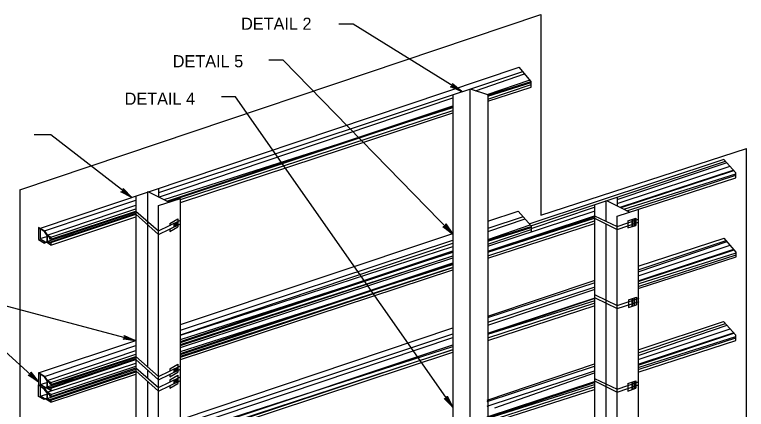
# Model space of a CAD drawing. Extents: x 650495 to 652241, y 298458 to 299646.
# Drawn here: x 651654.1 to 651834.8, y 298779.7 to 298877.1 of the extents above; entities that cross this region are included whole.
import ezdxf

# ---------------------------------------------------------------- set-up
doc = ezdxf.new("R2010")
doc.units = 0
doc.layers.add('2', color=7, linetype='Continuous')
doc.layers.add('3', color=7, linetype='Continuous')

# ---------------------------------------------------------------- blocks, each defined once
blk = doc.blocks.new('RARROW')
at = {"layer": '3'}
blk.add_lwpolyline([(-2.2695, 0.285), (-2.184875, 0.12075), (0, 0), (-2.2695, 0.285), (-2.38575, 0.384625), (0, 0), (-2.183125, -0.108), (-2.262875, -0.2705), (0, 0), (-2.38575, -0.379125), (-2.262875, -0.2705)], dxfattribs=at)

msp = doc.modelspace()

# ---------------------------------------------------------------- linework, layer by layer
at = {"layer": '2'}
for p, q in [((651655.44, 298833.88), (651784.06, 298877.13)), ((651784.06, 298877.13), (651784.06, 298827.63)), ((651737.69, 298874.75), (651734.19, 298874.75)), ((651764.56, 298858.13), (651737.69, 298874.75)), ((651720.44, 298865.88), (651716.94, 298865.88)), ((651762.31, 298823), (651720.44, 298865.88)), ((651660.31, 298824.38), (651778.69, 298864.13)), ((651779.56, 298863), (651689.69, 298833.13)), ((651767.97, 298858.31), (651780.06, 298862.5)), ((651781.69, 298860.63), (651778.69, 298864.13)), ((651770.81, 298857.42), (651781.44, 298861)), ((651781.69, 298859.25), (651781.69, 298860.75)), ((651770.94, 298857.25), (651781.69, 298860.63)), ((651770.94, 298857), (651781.69, 298860.38)), ((651770.94, 298856.25), (651781.69, 298859.88)), ((651770.94, 298855.75), (651781.69, 298859.25)), ((651762.31, 298857.27), (651762.31, 298770.13)), ((651766.56, 298858.68), (651766.56, 298771.88)), ((651770.94, 298857.38), (651766.67, 298858.72)), ((651770.94, 298857.38), (651770.94, 298770.38)), ((651689.69, 298832.13), (651762.31, 298856.63)), ((651708.69, 298856.88), (651705.19, 298856.88)), ((651762.31, 298780.25), (651708.69, 298856.88)), ((651691.06, 298831.5), (651762.31, 298854.25)), ((651691.69, 298831.13), (651762.31, 298854.63)), ((651692.06, 298831), (651762.31, 298854.38)), ((651695.06, 298831.5), (651762.31, 298853.5)), ((651695.06, 298830.75), (651762.31, 298852.88)), ((651663.06, 298847.5), (651658.94, 298847.5)), ((651683.06, 298832), (651663.06, 298847.5)), ((651784.06, 298827.63), (651834.81, 298844.13)), ((651834.81, 298733.38), (651834.81, 298844.13)), ((651781.19, 298825.5), (651829.31, 298841.5)), ((651781.56, 298825), (651829.69, 298841)), ((651832.19, 298838.13), (651829.19, 298841.5)), ((651802.94, 298831.5), (651830.06, 298840.63)), ((651802.94, 298830.5), (651830.81, 298839.75)), ((651803.69, 298829.63), (651831.56, 298838.75)), ((651803.94, 298829.5), (651831.69, 298838.63)), ((651804.56, 298829.13), (651832.19, 298837.88)), ((651805.31, 298828.75), (651832.19, 298837.5)), ((651832.19, 298836.88), (651832.19, 298838.13)), ((651802.94, 298827.38), (651832.19, 298836.88)), ((651655.44, 298834), (651655.44, 298674)), ((651689.69, 298834.25), (651689.69, 298832.13)), ((651684.06, 298832.38), (651684.06, 298664.13)), ((651687.06, 298833.5), (651692.31, 298830.88)), ((651687.06, 298790.13), (651687.06, 298833.5)), ((651689.69, 298830), (651695.06, 298831.75)), ((651695.06, 298661.88), (651695.06, 298831.75)), ((651802.94, 298832), (651802.94, 298830)), ((651661.56, 298823.75), (651684.06, 298831.38)), ((651662.19, 298822.75), (651684.06, 298830.13)), ((651689.69, 298659.25), (651689.69, 298830)), ((651797.31, 298830.25), (651797.31, 298704.5)), ((651800.19, 298826.13), (651800.19, 298831.25)), ((651800.31, 298831.25), (651806.06, 298828.38)), ((651662.19, 298821.13), (651684.06, 298828.5)), ((651663.06, 298822.25), (651684.06, 298829.25)), ((651663.06, 298821.75), (651684.06, 298828.63)), ((651684.06, 298828.63), (651689.69, 298823.75)), ((651770.94, 298820), (651797.44, 298828.75)), ((651770.94, 298826.13), (651778.44, 298828.63)), ((651778.44, 298828.63), (651781.69, 298825)), ((651781.69, 298824.38), (651797.31, 298829.63)), ((651808.19, 298702.25), (651808.19, 298829.13)), ((651662.81, 298821), (651684.06, 298828.13)), ((651663.06, 298820.88), (651684.06, 298827.88)), ((651663.06, 298820.25), (651684.06, 298827.25)), ((651684.06, 298827.88), (651689.69, 298822.88)), ((651684.06, 298827.25), (651684.06, 298827.25)), ((651689.69, 298823.75), (651695.06, 298826.38)), ((651692.44, 298825.63), (651694.44, 298826.75)), ((651694.44, 298826.75), (651694.44, 298824.75)), ((651770.94, 298818.75), (651797.31, 298827.5)), ((651779.69, 298827.25), (651770.94, 298824.38)), ((651770.94, 298818.5), (651797.31, 298827.25)), ((651770.94, 298818.5), (651797.31, 298826.88)), ((651770.94, 298823.63), (651780.19, 298826.75)), ((651797.31, 298827.5), (651802.94, 298824.88)), ((651797.31, 298826.88), (651802.94, 298824.13)), ((651802.94, 298699.63), (651802.94, 298827.38)), ((651802.94, 298824.88), (651808.19, 298826.63)), ((651805.56, 298826.25), (651807.56, 298826.88)), ((651806.56, 298826.63), (651806.56, 298824.75)), ((651806.81, 298826.63), (651806.81, 298824.88)), ((651807.19, 298826.75), (651807.19, 298825)), ((651807.56, 298826.88), (651807.56, 298825.13)), ((651660.06, 298824.63), (651660.06, 298824.63)), ((651661.56, 298823.75), (651660.06, 298824.63)), ((651660.06, 298824.63), (651660.06, 298821.63)), ((651660.06, 298824.63), (651661.56, 298823.75)), ((651689.69, 298822.88), (651695.06, 298825.5)), ((651692.44, 298825.63), (651692.44, 298825)), ((651692.44, 298823.63), (651694.44, 298824.75)), ((651693.44, 298825.63), (651693.44, 298824.75)), ((651693.69, 298825.75), (651693.69, 298824.88)), ((651694.06, 298825.88), (651694.06, 298825.13)), ((651694.31, 298826), (651694.31, 298825.25)), ((651770.94, 298817.63), (651797.31, 298826.25)), ((651770.94, 298817), (651797.31, 298825.63)), ((651770.94, 298821.63), (651781.44, 298825.25)), ((651770.94, 298821.5), (651781.69, 298824.88)), ((651770.94, 298821.25), (651781.69, 298824.63)), ((651781.69, 298825), (651781.69, 298823.5)), ((651800.19, 298702), (651800.19, 298825.5)), ((651802.94, 298824.13), (651808.19, 298825.88)), ((651805.56, 298826.25), (651805.56, 298824.5)), ((651805.56, 298824.5), (651807.56, 298825.13)), ((651660.44, 298824.25), (651660.44, 298821.75)), ((651661.44, 298823.63), (651660.44, 298824.25)), ((651661.44, 298823.63), (651662.06, 298822.63)), ((651661.56, 298823.75), (651662.19, 298822.75)), ((651662.06, 298822.75), (651662.06, 298821.13)), ((651662.19, 298821.13), (651668.69, 298823.25)), ((651663.06, 298822.25), (651662.19, 298822.75)), ((651663.06, 298822.25), (651669.56, 298824.38)), ((651663.06, 298821.75), (651669.56, 298823.88)), ((651692.44, 298824.25), (651692.44, 298823.63)), ((651695.06, 298800.63), (651762.31, 298823.13)), ((651770.94, 298820.5), (651781.69, 298824.13)), ((651660.06, 298821.63), (651661.56, 298820.75)), ((651660.44, 298821.88), (651662.06, 298822.38)), ((651661.69, 298821), (651660.44, 298821.75)), ((651661.44, 298821.25), (651660.44, 298821.75)), ((651661.69, 298821), (651662.06, 298821.13)), ((651662.81, 298822.13), (651662.19, 298822.5)), ((651662.81, 298822.13), (651662.19, 298822.5)), ((651662.19, 298822.5), (651662.19, 298821.13)), ((651662.81, 298820.75), (651662.19, 298821.13)), ((651662.81, 298822.13), (651662.81, 298821.88)), ((651662.81, 298821.75), (651662.81, 298822.13)), ((651663.06, 298821.75), (651662.81, 298821.88)), ((651663.06, 298821.75), (651662.81, 298821.75)), ((651662.81, 298821), (651662.81, 298820.75)), ((651663.06, 298820.88), (651662.81, 298821)), ((651662.81, 298821), (651662.81, 298820.75)), ((651663.06, 298820.88), (651662.81, 298821)), ((651663.06, 298822.25), (651663.06, 298821.75)), ((651663.06, 298822.25), (651663.06, 298821.75)), ((651695.06, 298799.25), (651762.31, 298821.5)), ((651808.31, 298815.13), (651829.31, 298822)), ((651808.31, 298814.25), (651829.81, 298821.38)), ((651808.31, 298813.75), (651830.06, 298821.13)), ((651832.31, 298818.5), (651829.31, 298822)), ((651662.06, 298820.88), (651661.56, 298820.75)), ((651663.06, 298820.25), (651662.06, 298820.88)), ((651663.06, 298820.88), (651663.06, 298820.25)), ((651663.06, 298820.88), (651663.06, 298820.25)), ((651695.06, 298798.13), (651762.31, 298820.75)), ((651695.06, 298798), (651762.31, 298819.88)), ((651808.31, 298812.75), (651830.81, 298820.25)), ((651808.31, 298811.5), (651831.69, 298819.25)), ((651808.31, 298811.38), (651831.81, 298819.13)), ((651695.06, 298796.5), (651762.31, 298818.88)), ((651695.06, 298796.25), (651762.31, 298818.63)), ((651695.06, 298797), (651762.31, 298818.5)), ((651695.06, 298795.5), (651762.31, 298817.63)), ((651695.06, 298795.75), (651762.31, 298817.63)), ((651808.31, 298810.75), (651832.31, 298818.38)), ((651808.31, 298810.13), (651832.31, 298817.88)), ((651808.31, 298809.63), (651832.31, 298817.38)), ((651832.31, 298817.38), (651832.31, 298818.5)), ((651695.06, 298795), (651762.31, 298817.13)), ((651695.06, 298793.5), (651762.31, 298815.88)), ((651695.06, 298793.25), (651762.31, 298815.75)), ((651695.06, 298794), (651762.31, 298815.5)), ((651695.06, 298792.63), (651762.31, 298814.75)), ((651695.06, 298792.88), (651762.19, 298814.75)), ((651695.06, 298792), (651762.31, 298814.13)), ((651770.94, 298802.75), (651797.44, 298811.63)), ((651770.94, 298802.38), (651797.44, 298811)), ((651770.94, 298801.25), (651797.44, 298810)), ((651770.94, 298800.5), (651797.44, 298809.38)), ((651683.94, 298796.75), (651646.19, 298806.75)), ((651770.94, 298798.5), (651797.44, 298807.25)), ((651770.94, 298798.38), (651797.44, 298807.13)), ((651770.94, 298798.25), (651797.44, 298806.63)), ((651797.44, 298808), (651802.94, 298805.38)), ((651797.44, 298807.25), (651802.94, 298804.63)), ((651802.94, 298805.38), (651808.31, 298807.13)), ((651805.69, 298806.75), (651807.69, 298807.38)), ((651805.69, 298806.75), (651805.69, 298804.88)), ((651806.56, 298807), (651806.56, 298805.25)), ((651806.81, 298807.13), (651806.81, 298805.25)), ((651807.19, 298807.25), (651807.19, 298805.38)), ((651807.69, 298807.38), (651807.69, 298805.5)), ((651770.94, 298797.38), (651797.44, 298806)), ((651770.94, 298796.75), (651797.44, 298805.38)), ((651802.94, 298804.63), (651808.31, 298806.38)), ((651805.69, 298804.88), (651807.69, 298805.5)), ((651808.31, 298794.5), (651829.19, 298801.38)), ((651832.19, 298798), (651829.19, 298801.38)), ((651695.06, 298777.25), (651762.31, 298799.88)), ((651808.31, 298793.75), (651829.69, 298800.88)), ((651808.31, 298793.13), (651830.06, 298800.5)), ((651808.31, 298792.13), (651830.81, 298799.63)), ((651660.06, 298786.5), (651647.56, 298797.88)), ((651695.06, 298776), (651762.31, 298798.38)), ((651695.06, 298774.88), (651762.31, 298797.5)), ((651808.31, 298791), (651831.56, 298798.63)), ((651808.31, 298790.75), (651831.69, 298798.5)), ((651808.31, 298790.13), (651832.19, 298797.75)), ((651832.19, 298796.75), (651832.19, 298798)), ((651660.06, 298788.75), (651684.06, 298796.75)), ((651695.06, 298773.25), (651762.31, 298795.63)), ((651808.31, 298789.63), (651832.19, 298797.38)), ((651808.31, 298789), (651832.19, 298796.75)), ((651661.56, 298787.88), (651684.06, 298795.5)), ((651662.19, 298786.88), (651684.06, 298794.25)), ((651695.06, 298773.63), (651762.31, 298795.25)), ((651695.06, 298772.25), (651762.31, 298794.5)), ((651695.06, 298772.5), (651762.19, 298794.38)), ((651695.06, 298771.63), (651762.31, 298793.88)), ((651662.19, 298785.25), (651684.06, 298792.63)), ((651662.81, 298785.13), (651684.06, 298792.25)), ((651663.06, 298786.38), (651684.06, 298793.38)), ((651663.06, 298785.88), (651684.06, 298792.75)), ((651663.06, 298785), (651684.06, 298792)), ((651684.06, 298792.75), (651689.69, 298787.88)), ((651684.06, 298792), (651689.69, 298787)), ((651662.19, 298784), (651684.06, 298791.13)), ((651663.06, 298783.38), (651684.06, 298790.38)), ((651684.06, 298791.38), (651684.06, 298791.38)), ((651689.69, 298787.88), (651695.06, 298790.5)), ((651692.44, 298789.75), (651694.44, 298790.88)), ((651694.44, 298790.88), (651694.44, 298788.88)), ((651770.81, 298782), (651797.31, 298791)), ((651770.81, 298781.63), (651797.31, 298790.38)), ((651661.56, 298787.88), (651660.06, 298788.75)), ((651660.06, 298788.75), (651660.06, 298785.75)), ((651660.06, 298788.75), (651661.56, 298787.88)), ((651662.19, 298782.38), (651684.06, 298789.63)), ((651662.81, 298782.13), (651684.06, 298789.25)), ((651663.06, 298782.88), (651684.06, 298790)), ((651663.06, 298782), (651684.06, 298789)), ((651663.06, 298786.38), (651669.56, 298788.5)), ((651684.06, 298790), (651689.69, 298785.13)), ((651684.06, 298789.25), (651689.69, 298784.25)), ((651684.06, 298788.63), (651684.06, 298788.63)), ((651687.06, 298787.38), (651687.06, 298789.38)), ((651689.69, 298787), (651695.06, 298789.63)), ((651692.44, 298789.75), (651692.44, 298789.25)), ((651692.44, 298787.75), (651694.44, 298788.88)), ((651693.44, 298789.75), (651693.44, 298788.88)), ((651693.69, 298789.88), (651693.69, 298789)), ((651694.06, 298790), (651694.06, 298789.25)), ((651694.31, 298790.13), (651694.31, 298789.38)), ((651770.81, 298780.5), (651797.31, 298789.25)), ((651772.69, 298780.13), (651797.31, 298788.75)), ((651660.44, 298788.38), (651660.44, 298785.88)), ((651661.44, 298787.75), (651660.44, 298788.38)), ((651661.44, 298787.75), (651662.06, 298786.75)), ((651661.56, 298787.88), (651662.19, 298786.88)), ((651662.06, 298786.75), (651662.06, 298785.25)), ((651662.19, 298785.25), (651668.69, 298787.38)), ((651663.06, 298786.38), (651662.19, 298786.88)), ((651662.81, 298786.25), (651662.19, 298786.63)), ((651662.81, 298786.25), (651662.19, 298786.63)), ((651662.19, 298786.63), (651662.19, 298785.25)), ((651663.06, 298781.5), (651684.06, 298788.38)), ((651663.06, 298785.88), (651669.56, 298788)), ((651687.06, 298661.63), (651687.06, 298786.63)), ((651689.69, 298785.13), (651695.06, 298787.75)), ((651689.69, 298784.25), (651695.06, 298786.88)), ((651692.44, 298788.38), (651692.44, 298787.75)), ((651692.44, 298787), (651694.44, 298788.13)), ((651692.44, 298787), (651692.44, 298786.5)), ((651693.44, 298787), (651693.44, 298786.13)), ((651693.69, 298787.13), (651693.69, 298786.25)), ((651694.06, 298787.25), (651694.06, 298786.5)), ((651694.31, 298787.38), (651694.31, 298786.63)), ((651694.44, 298788.13), (651694.44, 298786.13)), ((651770.81, 298777.88), (651797.31, 298786.63)), ((651797.31, 298787.38), (651802.94, 298784.75)), ((651797.31, 298786.75), (651802.94, 298784)), ((651805.56, 298786.13), (651807.56, 298786.75)), ((651807.19, 298786.63), (651807.19, 298784.88)), ((651807.56, 298786.75), (651807.56, 298785)), ((651660.06, 298782.88), (651660.06, 298785.75)), ((651660.06, 298785.75), (651661.56, 298784.88)), ((651660.44, 298785.88), (651662.06, 298786.38)), ((651661.69, 298785.13), (651660.44, 298785.88)), ((651660.44, 298785.38), (651660.44, 298783)), ((651661.44, 298784.75), (651660.44, 298785.38)), ((651662.06, 298785), (651661.56, 298784.88)), ((651661.56, 298784.88), (651662.19, 298784)), ((651661.69, 298785.13), (651662.06, 298785.25)), ((651663.06, 298784.38), (651662.06, 298785)), ((651662.81, 298784.88), (651662.19, 298785.25)), ((651662.81, 298786.25), (651662.81, 298786)), ((651662.81, 298786), (651662.81, 298786.25)), ((651663.06, 298785.88), (651662.81, 298786)), ((651662.81, 298785.13), (651662.81, 298784.88)), ((651663.06, 298785), (651662.81, 298785.13)), ((651662.81, 298785.13), (651662.81, 298784.88)), ((651663.06, 298785), (651662.81, 298785.13)), ((651663.06, 298786.38), (651663.06, 298785.88)), ((651663.06, 298786.38), (651663.06, 298785.88)), ((651663.06, 298785), (651663.06, 298784.38)), ((651663.06, 298785), (651663.06, 298784.38)), ((651692.44, 298785), (651694.44, 298786.13)), ((651692.44, 298785.63), (651692.44, 298785)), ((651770.81, 298777.63), (651797.31, 298786.38)), ((651770.81, 298777.5), (651797.31, 298785.88)), ((651770.81, 298776.75), (651797.31, 298785.25)), ((651802.94, 298784.75), (651808.19, 298786.5)), ((651802.94, 298784), (651808.19, 298785.75)), ((651805.56, 298786.13), (651805.56, 298784.25)), ((651805.56, 298784.25), (651807.56, 298785)), ((651806.56, 298786.38), (651806.56, 298784.63)), ((651806.81, 298786.5), (651806.81, 298784.75)), ((651660.44, 298783), (651662.06, 298783.5)), ((651661.44, 298782.38), (651660.44, 298783)), ((651662.06, 298783.88), (651661.44, 298784.75)), ((651662.06, 298783.88), (651662.06, 298782.5)), ((651663.06, 298783.38), (651662.19, 298784)), ((651662.81, 298783.25), (651662.19, 298783.75)), ((651662.19, 298783.75), (651662.19, 298782.38)), ((651662.81, 298783), (651662.81, 298783.25)), ((651663.06, 298782.88), (651662.81, 298783)), ((651663.06, 298783.38), (651663.06, 298782.88)), ((651770.81, 298776.13), (651797.31, 298784.63)), ((651661.44, 298782.13), (651660.06, 298782.88)), ((651661.44, 298782.38), (651662.06, 298782.5)), ((651661.81, 298782.25), (651661.44, 298782.13)), ((651663.06, 298781.5), (651661.81, 298782.25)), ((651662.81, 298781.88), (651662.19, 298782.38)), ((651662.81, 298782.13), (651662.81, 298781.88)), ((651663.06, 298782), (651662.81, 298782.13)), ((651663.06, 298782), (651663.06, 298781.5))]:
    msp.add_line(p, q, dxfattribs=at)

# ---------------------------------------------------------------- block references
for p, xscale, yscale, rotation in [((651764.56, 298858.13), 1.257434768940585, 1.3092961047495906, -31.505889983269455), ((651683.06, 298832), 1.257434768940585, 1.3092961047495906, -37.30762065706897), ((651762.31, 298823), 1.2574347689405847, 1.3092961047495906, -45.88822886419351), ((651683.94, 298796.75), 1.2574347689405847, 1.3092961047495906, -14.467850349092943), ((651660.06, 298786.5), 1.2574347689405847, 1.3092961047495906, -42.00451374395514), ((651762.31, 298780.25), 1.2574347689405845, 1.3092961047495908, -54.475918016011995)]:
    msp.add_blockref('RARROW', p, dxfattribs=dict(at, xscale=xscale, yscale=yscale, rotation=rotation))

# ---------------------------------------------------------------- texts
for s, p in [('DETAIL 2', (651710.06, 298873.38)), ('DETAIL 5', (651693.19, 298864.13)), ('DETAIL 4', (651681.31, 298854.88))]:
    msp.add_text(s, height=3, dxfattribs=at).set_placement(p)

doc.saveas('drawing.dxf')
